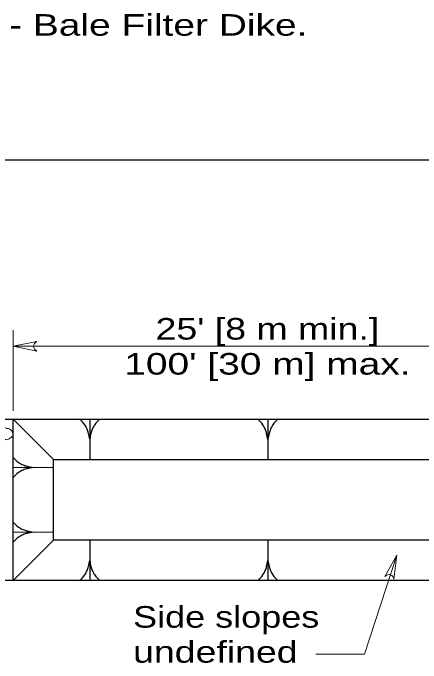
# Model space of a CAD drawing. Extents: x 1043.1 to 1101.1, y 672.4 to 716.4.
# Drawn here: x 1068.805 to 1071.835, y 702.851 to 707.676 of the extents above; entities that cross this region are included whole.
import ezdxf
from ezdxf.enums import TextEntityAlignment as Align

# ---------------------------------------------------------------- set-up
doc = ezdxf.new("R2010")
doc.units = 0
doc.header["$LTSCALE"] = 0.064
doc.layers.add('1', color=7, linetype='Continuous', lineweight=13)

msp = doc.modelspace()

# ---------------------------------------------------------------- linework, layer by layer
at = {"layer": '1', "lineweight": 25}
for p, q in [((1045.14425, 706.58517), (1075.64425, 706.58517)), ((1067.46633, 704.66183), (1073.97217, 704.66183)), ((1068.80542, 703.46258), (1068.80542, 704.66183)), ((1069.10525, 704.362), (1068.80542, 704.66183)), ((1069.30017, 704.66183), (1069.45017, 704.66183)), ((1069.37517, 704.66183), (1069.37517, 704.362)), ((1070.62292, 704.66067), (1070.77283, 704.66067)), ((1070.69783, 704.66067), (1070.69783, 704.362)), ((1068.80542, 704.22708), (1068.80542, 704.377)), ((1068.80542, 704.22708), (1068.80542, 704.377)), ((1068.80542, 703.74733), (1068.80542, 703.89725)), ((1068.80542, 703.46258), (1069.10525, 703.76233)), ((1069.37517, 703.76233), (1069.37517, 703.46258)), ((1070.69783, 703.76233), (1070.69783, 703.46258)), ((1073.97217, 703.46258), (1067.46633, 703.46258)), ((1069.45017, 703.46258), (1069.30017, 703.46258)), ((1070.77283, 703.46258), (1070.62292, 703.46258))]:
    msp.add_line(p, q, dxfattribs=at)
at = {"layer": '1'}
for p, q in [((1068.80542, 705.3215), (1068.80542, 704.72175)), ((1068.80542, 705.2015), (1072.58358, 705.2015)), ((1069.10525, 704.30208), (1068.80542, 704.30208)), ((1069.10525, 703.82233), (1068.80542, 703.82233))]:
    msp.add_line(p, q, dxfattribs=at)
for points in [[(1068.98192, 705.16625), (1068.80542, 705.2015), (1068.98192, 705.23683), (1068.98192, 705.23675)], [(1071.65558, 703.65067), (1071.41533, 702.91617), (1071.05442, 702.91617)], [(1071.56725, 703.49383), (1071.65558, 703.65067), (1071.63433, 703.47192), (1071.63425, 703.47192)]]:
    msp.add_lwpolyline(points, dxfattribs=at)
at = {"layer": '1', "lineweight": 25}
msp.add_lwpolyline([(1069.10525, 704.362), (1072.28367, 704.362), (1072.28367, 703.76233), (1069.10525, 703.76233)], close=True, dxfattribs=at)
at = {"layer": '1'}
for centre, start, end in [((1068.99627, 705.20147), 112.08789, 247.91402), ((1071.59622, 703.46929), 3.97532, 139.80144)]:
    msp.add_arc(centre, 0.03811, start, end, dxfattribs=at)
at = {"layer": '1', "lineweight": 25}
for points in [[(1069.37517, 704.512), (1069.36617, 704.5555), (1069.35608, 704.58675), (1069.33833, 704.61975), (1069.30017, 704.66183)], [(1069.45017, 704.66183), (1069.41192, 704.61975), (1069.39425, 704.58675), (1069.38417, 704.5555), (1069.37517, 704.512)], [(1070.69783, 704.51075), (1070.68883, 704.55425), (1070.67875, 704.58558), (1070.66117, 704.61858), (1070.62292, 704.66067)], [(1070.77283, 704.66067), (1070.73467, 704.61858), (1070.71692, 704.58558), (1070.70683, 704.55425), (1070.69783, 704.51075)], [(1068.80542, 704.377), (1068.84742, 704.33883), (1068.88042, 704.32117), (1068.91175, 704.31108), (1068.95533, 704.30208)], [(1068.80542, 704.377), (1068.84742, 704.33883), (1068.88042, 704.32117), (1068.91175, 704.31108), (1068.95533, 704.30208)], [(1068.95533, 704.30208), (1068.91175, 704.29308), (1068.88042, 704.283), (1068.84742, 704.26525), (1068.80542, 704.22708)], [(1068.95533, 704.30208), (1068.91175, 704.29308), (1068.88042, 704.283), (1068.84742, 704.26525), (1068.80542, 704.22708)], [(1068.80542, 703.89725), (1068.84742, 703.85908), (1068.88042, 703.8415), (1068.91175, 703.83133), (1068.95533, 703.82233)], [(1068.95533, 703.82233), (1068.91175, 703.81333), (1068.88042, 703.80325), (1068.84742, 703.78558), (1068.80542, 703.74733)], [(1069.30017, 703.46258), (1069.33833, 703.50467), (1069.35608, 703.53758), (1069.36617, 703.56883), (1069.37517, 703.6125)], [(1069.37517, 703.6125), (1069.38417, 703.56883), (1069.39425, 703.53758), (1069.41192, 703.50467), (1069.45017, 703.46258)], [(1070.62292, 703.46258), (1070.66117, 703.50467), (1070.67875, 703.53758), (1070.68883, 703.56883), (1070.69783, 703.6125)], [(1070.69783, 703.6125), (1070.70683, 703.56883), (1070.71692, 703.53758), (1070.73467, 703.50467), (1070.77283, 703.46258)]]:
    msp.add_spline(points, degree=3, dxfattribs=at)
at = {"layer": '1'}
msp.add_spline([(1068.67175, 704.58025), (1068.66842, 704.60133), (1068.6725, 704.62225), (1068.68292, 704.624), (1068.69717, 704.62333), (1068.71767, 704.608), (1068.73758, 704.59942), (1068.76017, 704.59217), (1068.77667, 704.58925), (1068.79225, 704.57825), (1068.80492, 704.55483), (1068.80617, 704.53992), (1068.78858, 704.52333), (1068.766, 704.509), (1068.73742, 704.51275), (1068.71758, 704.52083), (1068.69608, 704.54767), (1068.68275, 704.55942), (1068.67175, 704.58025)], degree=3, dxfattribs=at)

# ---------------------------------------------------------------- texts
for s, width, p in [('           Item 207 - Bale Filter Dike.', 1.35, (1066.68958, 707.507)), ('Side slopes', 1.25, (1069.697, 703.11317)), ('undefined', 1.3, (1069.697, 702.85317))]:
    msp.add_text(s, height=0.16, dxfattribs=dict(at, width=width)).set_placement(p)
for s, width, p in [("25' [8 m min.]", 1.3, (1070.69442, 705.2515)), ("100' [30 m] max.", 1.35, (1070.69446, 704.9915))]:
    msp.add_text(s, height=0.16, dxfattribs=dict(at, width=width)).set_placement(p, align=Align.CENTER)

doc.saveas('drawing.dxf')
